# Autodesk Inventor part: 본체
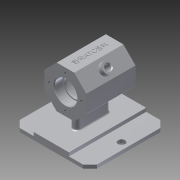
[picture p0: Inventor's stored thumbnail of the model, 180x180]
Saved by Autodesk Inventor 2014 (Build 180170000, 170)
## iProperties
Created: 2018-06
Part Number: 본체
Material: Aluminum 6061
Document SubType Name: Modeling
Designer: kh
Density: 2.71 g/cm^3
Appearance: Aluminum - Flat
Mass: 553.496 g
Surface Area: 603.098 cm^2
Volume: 204.242 cm^3
Author: kh
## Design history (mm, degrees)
sketch "Sketch1"
  geometry: L1 (-55, 55)-(55, 55); L2 (55, 55)-(55, -55); L3 (55, -55)-(-55, -55); L4 (-55, -55)-(-55, 55); L5 (-55, 55)-(55, -55); L6 (55, 55)-(-55, -55); 1 further point
  constraints: 12 end point, 2 midpoint, 2 parallel, 1 horizontal, 1 perpendicular
  dimensions: "d0" = 110 distance of L1.start L1.end; "d1" = 110 distance of L1.end L2.end
extrude "Extrusion1" new body sketch "Sketch1" distance "d2" = 5; taper "d3" = 0 deg
sketch "Sketch2"
  geometry: L1 (-55, 25)-(55, 25); L2 (55, 25)-(55, -25); L3 (55, -25)-(-55, -25); L4 (-55, -25)-(-55, 25); L5 (-55, 25)-(55, -25); L6 (55, 25)-(-55, -25); L7 (55, 55)-(-55, 55) reference; 1 further point
  constraints: 12 end point, 2 midpoint, 2 parallel, 1 horizontal, 1 perpendicular
  dimensions: "d4" = 110 distance of L1.start L1.end; "d5" = 30 distance between parallel lines of L1 L7
extrude "Extrusion2" join sketch "Sketch2" distance "d6" = 5; taper "d7" = 0 deg
sketch "Sketch4" dims "d12" = 60
  geometry: L1 (0, 0)-(0, 62); L2 (-12.426, 32)-(-30, 49.574); L3 (-30, 49.574)-(-30, 74.426); L4 (-30, 74.426)-(-12.426, 92); L5 (-12.426, 92)-(12.426, 92); L6 (12.426, 92)-(30, 74.426); L7 (30, 74.426)-(30, 49.574); L8 (30, 49.574)-(12.426, 32); L9 (12.426, 32)-(-12.426, 32); 3 further points
  constraints: 18 end point, 2 coincident, 1 midpoint, 1 point on line, 1 vertical, 1 vertical alignment, 19 other
  dimensions: "d11" = 62 distance of L1.start L1.end
extrude "Extrusion3" join sketch "Sketch4" stored distance "d13" = 70; taper "d14" = 0 deg
sketch "Sketch5"
  geometry: L1 (-19, 5)-(19, 5); L2 (24, 0)-(24, 0); L3 (19, -5)-(-19, -5); L4 (-24, 0)-(-24, 0); L5 (-24, 5)-(24, -5); L6 (24, 5)-(-24, -5); A1 r 5 centre (-19, 0) between (-19, 5) and (-24, 0); A2 r 5 centre (-19, 0) between (-24, 0) and (-19, -5); A3 r 5 centre (19, 0) between (19, -5) and (24, 0); A4 r 5 centre (19, 0) between (24, 0) and (19, 5); 1 further point
  constraints: 12 end point, 8 point on circle, 8 point on line, 8 tangent, 4 centre point, 3 equal radius, 2 midpoint, 2 parallel, 1 horizontal, 1 perpendicular
  dimensions: "d15" = 10 distance of L6.end L5.start; "d16" = 5 radius of A1; "d17" = 38 distance of A3.centre A1.centre
extrude "Extrusion4" join sketch "Sketch5" stored distance "d18" = 70; taper "d19" = 0 deg
sketch "Sketch6"
  geometry: L1 (-35, 74.426)-(35, 74.426) reference; L2 (-35, 49.574)-(-35, 74.426) reference; L3 (-35, 49.574)-(35, 49.574) reference; L4 (35, 74.426)-(35, 49.574) reference; L5 (35, 62)-(-35, 62); L6 (35, 62)-(35, 78); L7 (35, 78)-(23, 78); L8 (23, 78)-(23, 76); L9 (23, 76)-(20, 76); L10 (20, 76)-(20, 87); L11 (20, 87)-(-20, 87); L12 (-20, 87)-(-20, 76); L13 (-20, 76)-(-23, 76); L14 (-23, 76)-(-23, 78); L15 (-23, 78)-(-35, 78); L16 (-35, 78)-(-35, 62); 1 further point
  constraints: 24 end point, 5 perpendicular, 4 parallel, 2 midpoint, 1 collinear, 1 point on line
  dimensions: "d28" = 32 diameter of L7 L5; "d29" = 12 distance of L6.end L7.end; "d30" = 28 diameter of L9 L5; "d31" = 50 diameter of L11 L5; "d32" = 28 diameter of L13 L5; "d33" = 32 diameter of L15 L5; "d34" = 12 distance of L14.end L15.end; "d35" = 3 distance of L12.end L13.end; "d36" = 3 distance of L8.end L9.end
revolve "Revolution1" sketch "Sketch6" stored, may be unused: angle "d37" = 90 deg
chamfer "Chamfer1" distance "d38" = 1; stored, may be unused: second distance "d39" = 2, angle "d40" = 45 deg
workplane "Work Plane2"
  workplane "Work Plane1"
sketch "Sketch7"
  geometry: L1 (-70, -24.853)-(-70, 0) reference; L2 (0, 0)-(0, -24.853) reference; L3 (-70, -12.426)-(0, -12.426); C1 r 8 at (-35, -12.426); 1 further point
  constraints: 3 midpoint, 2 end point, 1 centre point
  dimensions: "d42" = 16 diameter of C1
extrude "Extrusion5" join sketch "Sketch7" stored distance "d43" = 70; taper "d44" = 0 deg
hole "Hole1" diameter "d47" = 8; stored, may be unused: countersink angle "d51" = 90 deg, drill point angle "d53" = 118 deg; dims "d45" = 10, "d46" = 10, "d48" = 6, "d49" = 4, "d50" = 2, "d52" = 30
chamfer "Chamfer2" distance "d54" = 1; stored, may be unused: second distance "d55" = 2, angle "d56" = 45 deg
sketch "Sketch8"
  geometry: L1 (59.887, 8.824)-(10.113, 8.824); L2 (10.113, 8.824)-(10.113, 16.029); L3 (10.113, 16.029)-(59.887, 16.029); L4 (59.887, 16.029)-(59.887, 8.824); L5 (59.887, 8.824)-(10.113, 16.029); L6 (70, 24.853)-(70, 0) reference; L7 (70, 0)-(0, 0) reference; L8 (70, -17.574)-(0, -17.574) reference; 3 further points
  constraints: 2 end point, 1 midpoint, 2 other
  dimensions: "d57" = 35 distance from line of point (35, 12.426) L6; "d59" = 30 distance from line of point (35, 12.426) L8
emboss "Emboss1" sketch "Sketch8" dims "d0" = 110, "d1" = 110, "d11" = 62, "d12" = 60, "d60" = 0.5, "d61" = 0
sketch "Sketch9" dims "d62" = 46
  geometry: L1 (-62, 0)-(-85, 0); C1 r 17 at (-62, 0) reference; 2 further points
  constraints: 2 coincident, 2 end point, 1 horizontal, 1 horizontal alignment, 2 other
hole "Hole2" sketch "Sketch9" at (-85, 0) diameter "d63" = 3.459; stored, may be unused: countersink angle "d67" = 90 deg, drill point angle "d69" = 118 deg; dims "d64" = 8, "d65" = 4, "d66" = 2, "d68" = 10
pattern_circular "Circular Pattern1" dims angle "d71" = 360 deg
mirror "Mirror1"
fillet "Fillet1" dims "d73" = 0.3
fillet "Fillet2" dims "d74" = 3
fillet "Fillet3" dims "d75" = 1
sketch "Sketch10"
  geometry: L1 (-55, -55)-(-55, 55) reference; L2 (-55, 55)-(55, 55) reference; L3 (0, 0)-(28.516, 0); C1 r 5 at (0, 45); C2 r 5 at (0, -45)
  constraints: 2 centre point, 2 end point, 1 parallel, 1 symmetric about line, 1 other
  dimensions: "d76" = 10 diameter of C1; "d77" = 55 distance from line of L1 C1.centre; "d78" = 10 distance from line of C1.centre L2
extrude "Extrusion6" cut sketch "Sketch10" stored distance "d79" = 70; taper "d80" = 0 deg
chamfer "Chamfer3" distance "d81" = 10; stored, may be unused: second distance "d82" = 2, angle "d83" = 45 deg
fillet "Fillet4" dims "d84" = 2
body "Solid1"
node "Projected Loop1"
other parameters: "d41" = 7
